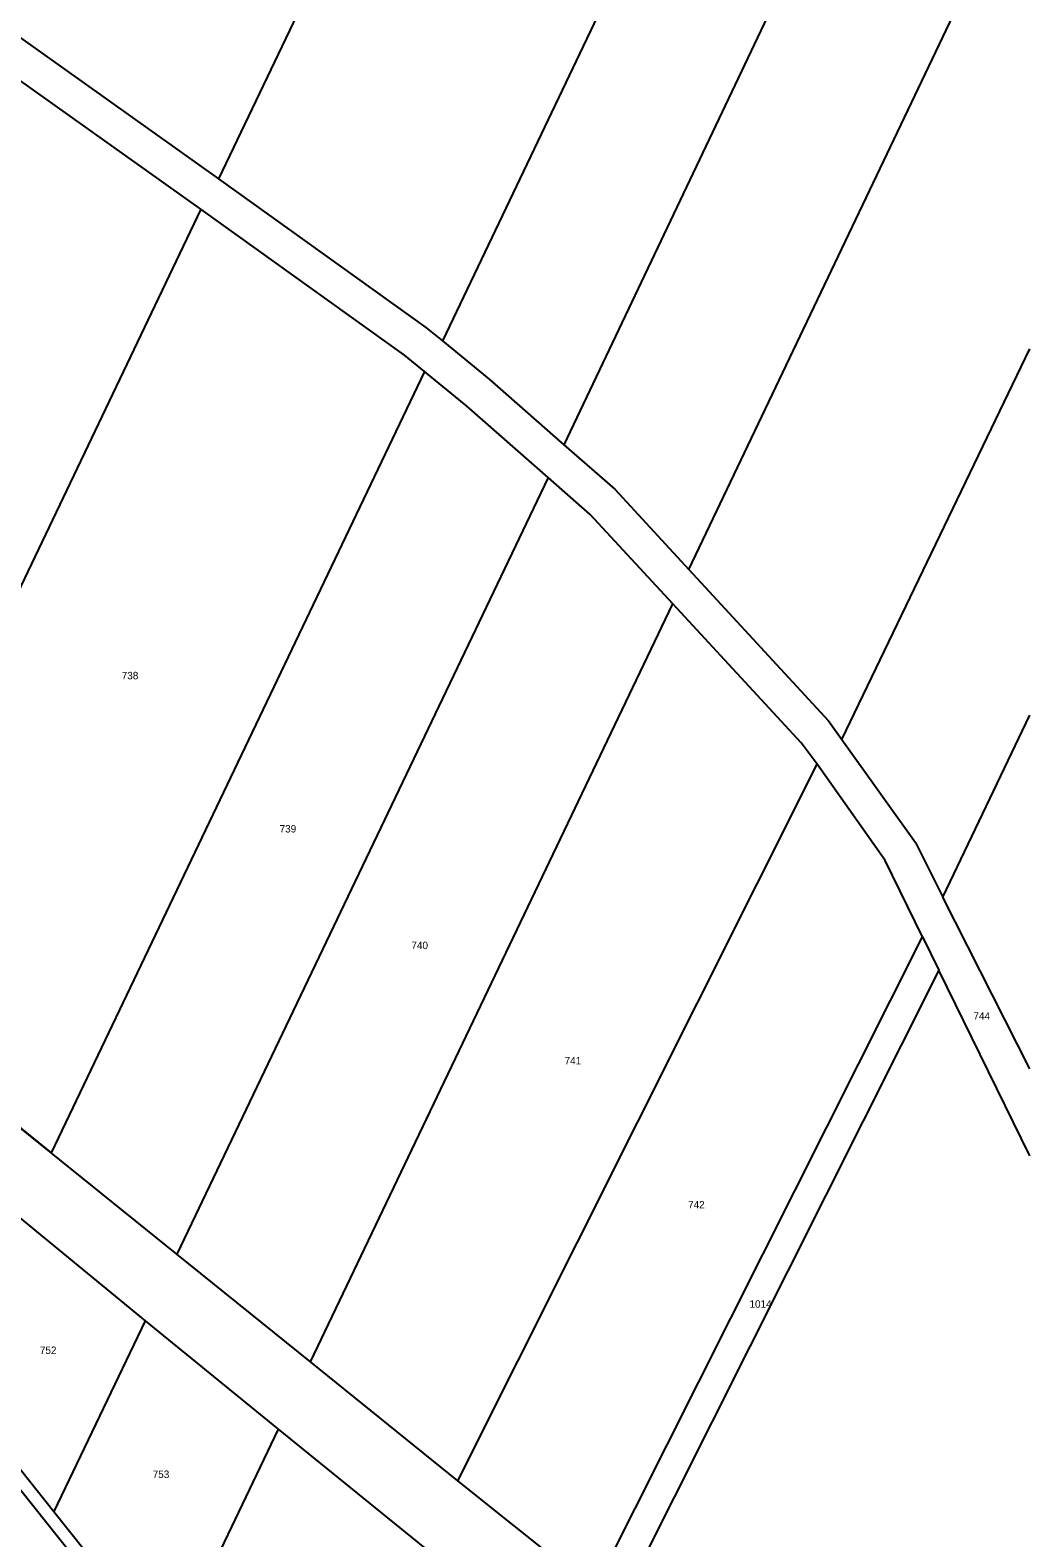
# Model space of a CAD drawing. Extents: x -504997 to -503568, y -1079870 to -1078007.
# Drawn here: x -503893.5 to -503665.3, y -1079531.2 to -1079186.7 of the extents above; entities that cross this region are included whole.
import ezdxf

# ---------------------------------------------------------------- set-up
doc = ezdxf.new("R2010")
doc.units = 0
for name, color, linetype in [('Hranice parcel', 7, 'Continuous'), ('Parcelní čísla', 7, 'Continuous'), ('Vrstva 54', 7, 'Continuous')]:
    doc.layers.add(name, color=color, linetype=linetype)

msp = doc.modelspace()

# ---------------------------------------------------------------- linework, layer by layer
at = {"layer": 'Hranice parcel'}
for p, q in [((-503905.42, -1079181.64), (-503850.5, -1079220.7)), ((-503854.56, -1079227.62), (-503908.92, -1079188.96)), ((-503854.56, -1079227.62), (-503938.33, -1079402.97)), ((-503803.5, -1079264.76), (-503888.76, -1079443.21)), ((-503775.28, -1079288.96), (-503860.04, -1079466.37)), ((-503829.57, -1079490.93), (-503746.84, -1079317.77)), ((-503795.86, -1079518.12), (-503713.84, -1079354.4)), ((-503665.31, -1079423.99), (-503685.15, -1079384.78)), ((-503764.74, -1079543.01), (-503689.81, -1079393.87)), ((-503689.81, -1079393.87), (-503686.06, -1079401.52)), ((-503686.06, -1079401.52), (-503759.31, -1079547.3)), ((-503860.04, -1079466.37), (-503888.76, -1079443.21)), ((-503895.86, -1079458.07), (-503867.31, -1079481.6)), ((-503829.57, -1079490.93), (-503860.04, -1079466.37)), ((-503867.31, -1079481.6), (-503888.1, -1079525.12)), ((-503867.31, -1079481.6), (-503836.94, -1079506.3)), ((-503795.86, -1079518.12), (-503829.57, -1079490.93)), ((-503912.97, -1079493.9), (-503888.1, -1079525.12)), ((-503836.94, -1079506.3), (-503861.75, -1079558.21)), ((-503836.94, -1079506.3), (-503794.37, -1079540.85)), ((-503764.74, -1079543.01), (-503795.86, -1079518.12)), ((-503888.1, -1079525.12), (-503861.75, -1079558.21))]:
    msp.add_line(p, q, dxfattribs=at)
for points in [[(-503685.33, -1078875.01), (-503691.77, -1078888.48), (-503771.35, -1079055.04), (-503850.5, -1079220.7)], [(-503665.31, -1078976.5), (-503713.43, -1079077.41), (-503799.42, -1079257.75)], [(-503665.31, -1079057.52), (-503694.3, -1079118.54), (-503771.69, -1079281.46)], [(-503743.13, -1079309.99), (-503665.31, -1079146.6)], [(-503850.5, -1079220.7), (-503803.2, -1079254.66), (-503799.42, -1079257.75)], [(-503803.5, -1079264.76), (-503808.09, -1079261), (-503854.56, -1079227.62)], [(-503799.42, -1079257.75), (-503788.76, -1079266.5), (-503771.69, -1079281.46)], [(-503708.2, -1079348.82), (-503665.31, -1079259.56)], [(-503775.28, -1079288.96), (-503793.94, -1079272.6), (-503803.5, -1079264.76)], [(-503771.69, -1079281.46), (-503760.08, -1079291.63), (-503743.13, -1079309.99)], [(-503746.84, -1079317.77), (-503765.67, -1079297.37), (-503775.28, -1079288.96)], [(-503743.13, -1079309.99), (-503711.27, -1079344.49), (-503708.2, -1079348.82)], [(-503713.84, -1079354.4), (-503717.5, -1079349.54), (-503746.84, -1079317.77)], [(-503685.15, -1079384.78), (-503665.31, -1079343.22)], [(-503708.2, -1079348.82), (-503691.45, -1079372.34), (-503685.15, -1079384.78)], [(-503689.81, -1079393.87), (-503698.35, -1079376.44), (-503713.84, -1079354.4)], [(-503888.76, -1079443.21), (-503936.1, -1079405.04), (-503938.33, -1079402.97)], [(-503665.31, -1079443.9), (-503686.06, -1079401.52)], [(-503697.84, -1079765.64), (-503779.17, -1079666.7), (-503806.76, -1079632.06), (-503843.08, -1079586.46), (-503955.21, -1079445.68)]]:
    msp.add_lwpolyline(points, dxfattribs=at)
at = {"layer": 'Vrstva 54'}
msp.add_lwpolyline([(-504259.1, -1079048.24), (-504191.97, -1079119.35), (-504187.04, -1079125.02), (-504168.33, -1079151.66), (-504150.39, -1079177.22), (-504141.49, -1079189.89), (-504109.47, -1079227.67), (-504070.38, -1079273.8), (-504043.38, -1079305.66), (-504041.43, -1079307.47), (-504008.27, -1079338.19), (-503988.82, -1079356.2), (-503938.33, -1079402.97), (-503888.76, -1079443.21)], dxfattribs=at)

# ---------------------------------------------------------------- texts
at = {"layer": 'Parcelní čísla'}
for s, p in [('738', (-503872.63, -1079335.04)), ('739', (-503836.59, -1079370.03)), ('740', (-503806.5, -1079396.67)), ('744', (-503678.19, -1079412.8)), ('741', (-503771.52, -1079423.01)), ('742', (-503743.33, -1079455.91)), ('1014', (-503729.32, -1079478.59)), ('752', (-503891.32, -1079489.16)), ('753', (-503865.56, -1079517.49))]:
    msp.add_text(s, height=1.7, dxfattribs=at).set_placement(p)

doc.saveas('drawing.dxf')
